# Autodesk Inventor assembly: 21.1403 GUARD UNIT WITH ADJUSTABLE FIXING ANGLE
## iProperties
Created: 2007-01
Part Number: 21.1403 GUARD UNIT WITH ADJUSTABLE FIXING ANGLE
Document SubType Name: Assembly
Designer: Andy Moles
Author: Andy Moles
